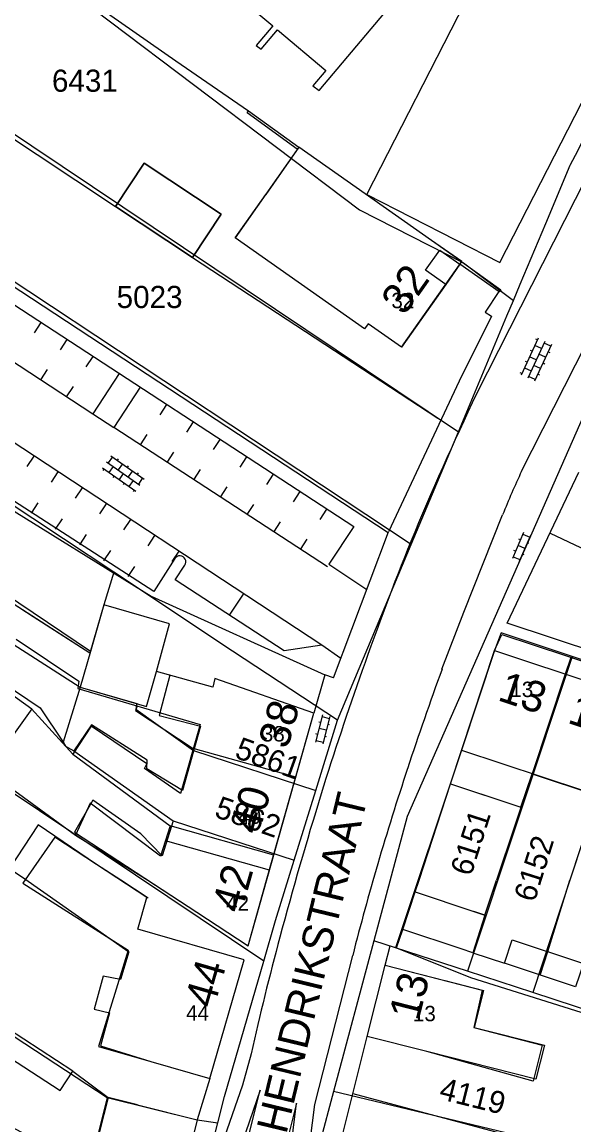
# Model space of a CAD drawing. Extents: x 148816 to 151297, y 399515 to 402500.
# Drawn here: x 150544.5 to 150589.4, y 399730.1 to 399819.8 of the extents above; entities that cross this region are included whole.
import ezdxf

# ---------------------------------------------------------------- set-up
doc = ezdxf.new("R2010")
doc.units = 0
for name, color, linetype in [('B01 Hoofdgebouw  [D] Norm', 7, 'Continuous'), ('B01 Hoofdgebouw  [T] Norm', 7, 'Continuous'), ('B01 hoofgebouw', 7, 'Continuous'), ('B02 Bijgebouw  [D] Norm', 7, 'Continuous'), ('B03 Overig opstal  [D] Norm', 7, 'Continuous'), ('B07 Tussenmuur  [D] Norm', 7, 'Continuous'), ('G01 perceelsgrens', 7, 'Continuous'), ('Q19 Overig lijnvormig object  [D] Gem', 7, 'Continuous'), ('S02 Open verharding  Norm', 7, 'Continuous'), ('T01 Muur  [T] Gem', 7, 'Continuous'), ('T04 Haag heg  [D] Gem', 7, 'Continuous'), ('V00 Kant verharding algemeen  [T] Norm', 7, 'Continuous'), ('V00 Kant verharding algemeen secundair  [T] Gem', 7, 'Continuous'), ('Z01 perceelnummer', 7, 'Continuous'), ('Z02 huisnummer', 7, 'Continuous'), ('Z02 Huisnummer  [Tekst] Norm', 7, 'Continuous'), ('Z06 straatnaam', 7, 'Continuous')]:
    doc.layers.add(name, color=color, linetype=linetype)

msp = doc.modelspace()

# ---------------------------------------------------------------- linework, layer by layer
at = {"layer": 'B01 Hoofdgebouw  [D] Norm'}
for p, q in [((150567.028, 399809.594), (150561.87, 399802.23)), ((150544.071, 399769.604), (150549.156, 399766.191)), ((150549.156, 399766.191), (150549.081, 399765.583)), ((150549.081, 399765.583), (150559.014, 399762.662)), ((150550.155, 399762.541), (150548.663, 399760.255)), ((150554.681, 399759.457), (150550.155, 399762.541)), ((150559.014, 399762.662), (150557.428, 399757.054)), ((150548.663, 399760.255), (150556.597, 399754.414)), ((150554.504, 399759.076), (150554.681, 399759.457)), ((150557.428, 399757.054), (150554.504, 399759.076)), ((150550.094, 399756.277), (150548.882, 399753.661)), ((150555.791, 399751.952), (150550.094, 399756.277)), ((150545.86, 399754.517), (150543.533, 399750.961)), ((150550.61, 399751.29), (150545.86, 399754.517)), ((150556.597, 399754.414), (150555.791, 399751.952)), ((150565.001, 399752.042), (150556.597, 399754.414)), ((150548.882, 399753.661), (150554.773, 399750)), ((150564.655, 399750.815), (150556.2, 399753.201)), ((150543.533, 399750.961), (150544.779, 399750.127)), ((150544.779, 399750.127), (150553.223, 399744.181)), ((150554.773, 399750), (150558.74, 399747.4)), ((150553.223, 399744.181), (150552.549, 399741.944)), ((150586.642, 399742.299), (150587.27, 399744.198)), ((150551.151, 399742.217), (150550.404, 399739.523)), ((150552.549, 399741.944), (150551.151, 399742.217)), ((150550.404, 399739.523), (150551.65, 399739.224)), ((150551.65, 399739.224), (150550.928, 399736.53)), ((150550.928, 399736.53), (150555, 399735.27)), ((150551.538, 399732.332), (150550.091, 399726.654)), ((150553.92, 399731.74), (150551.538, 399732.332))]:
    msp.add_line(p, q, dxfattribs=at)
for points in [[(150579.368, 399757.845), (150585.088, 399755.952), (150585.991, 399758.667), (150596.457, 399755.187)], [(150581.948, 399741.073), (150581.259, 399738.024), (150586.801, 399736.605)], [(150586.801, 399736.605), (150586.08, 399733.683), (150577.44, 399736.07)]]:
    msp.add_lwpolyline(points, dxfattribs=at)
at = {"layer": 'B01 Hoofdgebouw  [T] Norm'}
for p, q in [((150552.15, 399804.78), (150554.48, 399808.3)), ((150554.48, 399808.3), (150560.73, 399804.15)), ((150558.39, 399800.64), (150552.15, 399804.78)), ((150560.73, 399804.15), (150558.39, 399800.64)), ((150572.38, 399794.84), (150561.87, 399802.23)), ((150578.98, 399798.44), (150575.39, 399793.34)), ((150572.67, 399795.23), (150572.38, 399794.84)), ((150575.39, 399793.34), (150572.67, 399795.23)), ((150545.46, 399771.43), (150540.22, 399774.78)), ((150551.19, 399772.4), (150550.06, 399768.47)), ((150556.54, 399770.86), (150551.19, 399772.4)), ((150550.06, 399768.47), (150545.46, 399771.43)), ((150555.46, 399766.97), (150556.54, 399770.86)), ((150579.368, 399757.845), (150582.95, 399768.67)), ((150582.95, 399768.67), (150599.64, 399763.12)), ((150560.04, 399765.7), (150555.46, 399766.97)), ((150560.22, 399766.41), (150560.04, 399765.7)), ((150568.26, 399763.59), (150560.22, 399766.41)), ((150564.425, 399750), (150568.26, 399763.59)), ((150552.58, 399750), (150550.61, 399751.29)), ((150554.79, 399748.55), (150552.58, 399750)), ((150562.92, 399744.66), (150564.425, 399750)), ((150575.49, 399746), (150576.5, 399749.05)), ((150576.5, 399749.05), (150581.25, 399747.47)), ((150553.95, 399746.02), (150554.7, 399748.61)), ((150558.74, 399747.4), (150562.92, 399744.66)), ((150562.59, 399743.53), (150553.95, 399746.02)), ((150580.23, 399744.42), (150575.49, 399746)), ((150559.81, 399733.88), (150562.59, 399743.53)), ((150572.59, 399737.3), (150574.06, 399743.09)), ((150574.06, 399743.09), (150581.948, 399741.073)), ((150577.44, 399736.07), (150572.59, 399737.3)), ((150555, 399735.27), (150559.81, 399733.88)), ((150553.92, 399731.74), (150558.78, 399730.54)), ((150558.78, 399730.54), (150555, 399715.27))]:
    msp.add_line(p, q, dxfattribs=at)
msp.add_lwpolyline([(150578.98, 399798.44), (150577.34, 399799.59), (150578.49, 399801.227), (150580.129, 399800.078), (150580.277, 399800.266), (150567.028, 399809.594)], dxfattribs=at)
at = {"layer": 'B01 hoofgebouw'}
for points in [[(150577.83, 399802.01), (150567.036, 399809.584), (150564.35, 399805.76)], [(150552.15, 399804.78), (150558.39, 399800.64), (150560.73, 399804.15), (150554.48, 399808.3), (150552.15, 399804.78)], [(150575.39, 399793.34), (150572.67, 399795.23), (150572.38, 399794.84), (150561.87, 399802.23), (150564.35, 399805.76)], [(150575.39, 399793.34), (150580.278, 399800.291), (150577.83, 399802.01)], [(150558.74, 399747.4), (150562.92, 399744.66), (150568.26, 399763.59), (150560.22, 399766.41), (150560.04, 399765.7), (150555.46, 399766.97), (150556.54, 399770.86), (150551.19, 399772.4), (150550.06, 399768.47), (150540.22, 399774.78), (150539.07, 399772.99)], [(150539.07, 399772.99), (150538.728, 399772.454), (150549.263, 399765.698), (150554.674, 399764.14), (150555.46, 399766.97)], [(150579.368, 399757.845), (150582.95, 399768.67), (150599.64, 399763.12), (150598.91, 399760.86), (150620.1, 399753.84), (150620.85, 399756.1), (150632.13, 399752.36), (150630.56, 399747.62)], [(150556.57, 399766.662), (150555.69, 399763.406), (150559.036, 399762.518), (150557.585, 399757.294), (150554.685, 399759.06), (150554.714, 399759.754), (150550.195, 399762.627), (150548.768, 399760.515), (150556.832, 399754.828), (150555.925, 399751.979), (150554.192, 399753.766), (150550.299, 399756.503), (150548.822, 399753.901), (150558.74, 399747.4)], [(150580.269, 399760.57), (150596.652, 399755.155), (150596.036, 399753.294), (150618.026, 399746.009), (150618.684, 399747.993), (150629.497, 399744.411), (150630.56, 399747.62)], [(150579.368, 399757.845), (150584.115, 399756.274)], [(150550.61, 399751.29), (150547.224, 399753.509), (150544.598, 399749.759), (150553.184, 399744.316), (150550.754, 399736.497), (150555, 399735.27)], [(150555, 399735.27), (150559.81, 399733.88), (150562.59, 399743.53), (150553.95, 399746.02), (150554.699, 399748.61), (150550.61, 399751.29)], [(150580.23, 399744.421), (150575.49, 399746), (150576.5, 399749.05), (150581.25, 399747.47)], [(150581.25, 399747.47), (150582.166, 399747.165), (150581.177, 399744.106), (150580.23, 399744.421)], [(150577.44, 399736.07), (150572.59, 399737.3), (150574.06, 399743.09), (150578.91, 399741.85)], [(150578.91, 399741.85), (150582.042, 399741.049), (150581.277, 399738.037), (150586.991, 399736.586), (150586.292, 399733.831), (150577.44, 399736.07)], [(150553.92, 399731.74), (150551.463, 399732.347), (150550.034, 399726.575), (150540.675, 399731.527), (150539.134, 399728.318), (150549.308, 399723.108), (150547.671, 399717.193), (150554.88, 399715.29)], [(150553.92, 399731.74), (150558.78, 399730.54), (150555, 399715.27), (150554.88, 399715.29), (150554.11, 399712.06), (150554.34, 399711.91), (150545.9, 399698.83), (150538.61, 399703.59), (150541.34, 399707.78)]]:
    msp.add_lwpolyline(points, dxfattribs=at)
at = {"layer": 'B02 Bijgebouw  [D] Norm'}
for p, q in [((150582.166, 399747.165), (150581.25, 399747.47)), ((150582.166, 399747.165), (150581.177, 399744.106)), ((150581.177, 399744.106), (150580.23, 399744.42))]:
    msp.add_line(p, q, dxfattribs=at)
for points in [[(150545.354, 399763.926), (150542.124, 399759.47), (150539.598, 399761.301), (150542.828, 399765.757)], [(150584.379, 399745.154), (150590.163, 399743.242), (150589.535, 399741.343), (150583.751, 399743.255)], [(150548.679, 399734.489), (150543.371, 399737.938), (150542.347, 399736.362), (150547.655, 399732.913)]]:
    msp.add_lwpolyline(points, close=True, dxfattribs=at)
at = {"layer": 'B03 Overig opstal  [D] Norm'}
msp.add_line((150580.129, 399800.078), (150578.98, 399798.44), dxfattribs=at)
at = {"layer": 'B07 Tussenmuur  [D] Norm'}
for p, q in [((150588.683, 399766.764), (150585.991, 399758.667)), ((150588.683, 399766.764), (150585.991, 399758.667)), ((150566.788, 399758.373), (150558.465, 399760.722)), ((150566.788, 399758.373), (150558.465, 399760.722))]:
    msp.add_line(p, q, dxfattribs=at)
at = {"layer": 'G01 perceelsgrens'}
for points in [[(150589.099, 399808.13), (150589.122, 399808.185), (150589.71, 399809.3), (150601.431, 399833.535), (150603.833, 399838.516)], [(150545.002, 399824.898), (150571.96, 399804.509)], [(150604.416, 399818.758), (150601.281, 399812.394), (150599.073, 399807.818), (150596.886, 399803.311), (150590.138, 399787.704), (150575.84, 399755.196), (150573.128, 399745.085)], [(150537.849, 399814.725), (150580.009, 399786.458)], [(150587.102, 399803.381), (150589.099, 399808.13)], [(150576.166, 399777.284), (150532.256, 399806.347)], [(150571.96, 399804.509), (150580.411, 399800.191)], [(150585.036, 399798.471), (150587.102, 399803.381)], [(150580.411, 399800.191), (150584.475, 399797.137)], [(150584.475, 399797.137), (150585.036, 399798.471)], [(150580.009, 399786.458), (150583.954, 399795.897), (150584.475, 399797.137)], [(150551.994, 399775.056), (150547.928, 399777.763), (150525.787, 399792.428)], [(150550.097, 399768.597), (150522.284, 399787.353)], [(150576.166, 399777.284), (150577.906, 399781.427), (150580.009, 399786.458)], [(150518.839, 399782.361), (150546.033, 399764.013), (150547.883, 399761.218)], [(150570.17, 399763.009), (150576.166, 399777.284)], [(150564.198, 399743.427), (150519.987, 399773.049), (150514.769, 399776.465)], [(150551.994, 399775.056), (150551.19, 399772.4), (150550.097, 399768.597)], [(150570.17, 399763.009), (150561.645, 399768.63), (150551.994, 399775.056)], [(150490.322, 399772.344), (150518.769, 399753.768), (150551.463, 399732.347), (150558.78, 399730.54), (150560.452, 399730.286)], [(150589.256, 399768.196), (150583.47, 399770.128), (150582.95, 399768.67), (150580.27, 399760.57), (150574.887, 399744.504)], [(150550.097, 399768.597), (150549.263, 399765.698)], [(150589.256, 399768.196), (150580.733, 399742.602)], [(150594.474, 399766.455), (150589.256, 399768.196)], [(150594.474, 399766.455), (150586.049, 399740.873)], [(150549.263, 399765.698), (150547.883, 399761.218)], [(150549.263, 399765.698), (150553.885, 399764.368), (150553.794, 399763.902), (150558.486, 399760.54), (150568.415, 399757.309)], [(150568.415, 399757.309), (150570.17, 399763.009)], [(150547.883, 399761.218), (150548.085, 399760.913), (150548.768, 399760.515), (150556.832, 399754.828), (150566.666, 399751.626)], [(150566.666, 399751.626), (150568.415, 399757.309)], [(150564.198, 399743.427), (150565.156, 399746.725), (150566.666, 399751.626)], [(150573.128, 399745.085), (150569.86, 399732.829)], [(150574.887, 399744.504), (150573.128, 399745.085)], [(150580.733, 399742.602), (150574.887, 399744.504)], [(150560.452, 399730.286), (150561.002, 399732.427), (150564.198, 399743.427)], [(150586.049, 399740.873), (150580.733, 399742.602)], [(150591.249, 399739.182), (150586.049, 399740.873)], [(150569.86, 399732.829), (150566.525, 399720.322)], [(150593.91, 399727.057), (150569.86, 399732.829)], [(150558.519, 399722.699), (150558.929, 399724.354), (150560.452, 399730.286)]]:
    msp.add_lwpolyline(points, dxfattribs=at)
at = {"layer": 'Q19 Overig lijnvormig object  [D] Gem'}
for points in [[(150572.578, 399805.753), (150583.374, 399800.222), (150593.34, 399819.673), (150589.308, 399823.073), (150592.705, 399827.102), (150593.685, 399826.275), (150601.304, 399835.311), (150600.645, 399835.867), (150604.332, 399840.24), (150601.121, 399842.948), (150606.381, 399849.186), (150592.425, 399860.953), (150592.045, 399860.502)], [(150560.987, 399822.769), (150564.914, 399819.459), (150563.571, 399817.866), (150563.98, 399817.575), (150565.296, 399819.136), (150569.223, 399815.826), (150568.175, 399814.583), (150568.689, 399814.217), (150580.082, 399827.726)], [(150572.578, 399805.753), (150580.567, 399821.346), (150581.76, 399820.735), (150582.121, 399821.44)]]:
    msp.add_lwpolyline(points, dxfattribs=at)
at = {"layer": 'S02 Open verharding  Norm'}
for p, q in [((150586.487, 399794.061), (150585.102, 399791.066)), ((150586.424, 399793.925), (150586.288, 399793.988)), ((150587.031, 399793.81), (150585.647, 399790.814)), ((150586.004, 399793.018), (150585.868, 399793.081)), ((150587.576, 399793.558), (150586.191, 399790.563)), ((150586.759, 399793.22), (150586.214, 399793.471)), ((150587.513, 399793.422), (150586.969, 399793.674)), ((150587.303, 399792.968), (150587.439, 399792.905)), ((150585.585, 399792.11), (150585.448, 399792.173)), ((150586.339, 399792.312), (150585.794, 399792.564)), ((150587.093, 399792.514), (150586.549, 399792.766)), ((150586.884, 399792.06), (150587.02, 399791.997)), ((150585.165, 399791.202), (150585.029, 399791.265)), ((150585.375, 399791.656), (150585.919, 399791.404)), ((150586.674, 399791.606), (150586.129, 399791.858)), ((150586.464, 399791.153), (150586.6, 399791.09)), ((150586.254, 399790.699), (150585.709, 399790.95)), ((150551.421, 399784.016), (150554.127, 399782.128)), ((150551.887, 399784.422), (150551.544, 399783.93)), ((150551.764, 399784.508), (150554.471, 399782.62)), ((150552.297, 399784.136), (150552.383, 399784.259)), ((150551.077, 399783.524), (150553.784, 399781.636)), ((150551.201, 399783.438), (150551.115, 399783.315)), ((150551.954, 399783.644), (150551.611, 399783.152)), ((150552.707, 399783.85), (150552.364, 399783.358)), ((150553.117, 399783.564), (150553.203, 399783.687)), ((150553.527, 399783.278), (150553.184, 399782.786)), ((150553.937, 399782.992), (150554.023, 399783.115)), ((150552.021, 399782.866), (150551.935, 399782.743)), ((150552.774, 399783.072), (150552.431, 399782.58)), ((150552.841, 399782.294), (150552.755, 399782.171)), ((150553.251, 399782.008), (150553.594, 399782.5)), ((150554.347, 399782.706), (150554.004, 399782.214)), ((150553.661, 399781.722), (150553.575, 399781.599)), ((150585.308, 399778.276), (150584.393, 399776.166)), ((150585.05, 399777.68), (150584.912, 399777.74)), ((150585.859, 399778.038), (150584.944, 399775.928)), ((150585.249, 399778.139), (150585.799, 399777.9)), ((150584.652, 399776.763), (150584.514, 399776.822)), ((150585.401, 399776.983), (150584.851, 399777.221)), ((150585.738, 399777.382), (150585.6, 399777.441)), ((150584.453, 399776.304), (150585.003, 399776.065)), ((150585.34, 399776.464), (150585.202, 399776.524)), ((150568.965, 399763.457), (150568.401, 399761.228)), ((150568.806, 399762.827), (150568.66, 399762.864)), ((150568.928, 399763.312), (150569.51, 399763.165)), ((150569.547, 399763.31), (150568.983, 399761.081)), ((150569.533, 399762.643), (150569.387, 399762.68)), ((150568.561, 399761.858), (150568.415, 399761.895)), ((150569.265, 399762.195), (150568.683, 399762.343)), ((150569.288, 399761.674), (150569.142, 399761.711)), ((150568.438, 399761.373), (150569.02, 399761.226))]:
    msp.add_line(p, q, dxfattribs=at)
at = {"layer": 'T01 Muur  [T] Gem'}
for points in [[(150566.913, 399809.43), (150562.838, 399812.378), (150562.955, 399812.54), (150567.028, 399809.594)], [(150580.277, 399800.266), (150583.455, 399798.003), (150583.333, 399797.832), (150580.129, 399800.078)]]:
    msp.add_lwpolyline(points, dxfattribs=at)
at = {"layer": 'T04 Haag heg  [D] Gem'}
for p, q in [((150537.563, 399814.432), (150552.15, 399804.78)), ((150532.152, 399805.974), (150574.298, 399778.283)), ((150558.39, 399800.64), (150578.345, 399787.561)), ((150524.785, 399791.88), (150555.028, 399773.103)), ((150555.028, 399773.103), (150569.14, 399766.69)), ((150589.132, 399768.121), (150588.683, 399766.764)), ((150545.329, 399763.951), (150548.663, 399760.255)), ((150553.905, 399764.165), (150553.756, 399763.792)), ((150553.756, 399763.792), (150558.465, 399760.722)), ((150537.236, 399762.158), (150548.882, 399753.661)), ((150585.991, 399758.667), (150583.109, 399750)), ((150591.345, 399756.887), (150589.055, 399750)), ((150582.166, 399747.165), (150583.109, 399750)), ((150587.27, 399744.198), (150589.055, 399750)), ((150548.679, 399734.489), (150551.538, 399732.332)), ((150571.433, 399732.673), (150593.685, 399726.708))]:
    msp.add_line(p, q, dxfattribs=at)
msp.add_lwpolyline([(150545.036, 399825.01), (150557.051, 399816.621), (150562.955, 399812.54)], dxfattribs=at)
at = {"layer": 'V00 Kant verharding algemeen  [T] Norm'}
for p, q in [((150529.69, 399806.06), (150571.51, 399778.765)), ((150583.29, 399797.862), (150582.17, 399796.18)), ((150582.71, 399795.85), (150580.08, 399790.57)), ((150582.17, 399796.18), (150582.71, 399795.85)), ((150555.245, 399773.465), (150526.41, 399792.14)), ((150552.444, 399791.209), (150550.299, 399787.922)), ((150580.08, 399790.57), (150574.32, 399778.33)), ((150554.147, 399790.097), (150552.002, 399786.81)), ((150550.299, 399787.922), (150552.002, 399786.81)), ((150571.51, 399778.765), (150569.49, 399775.685)), ((150569.85, 399766.45), (150574.32, 399778.33)), ((150556.955, 399776.15), (150555.245, 399773.465)), ((150556.99, 399774.425), (150557.78, 399775.615)), ((150569.49, 399775.685), (150572.555, 399773.635)), ((150565.84, 399768.66), (150556.99, 399774.425)), ((150636.07, 399753.71), (150583.965, 399770.895)), ((150582.95, 399768.67), (150583.54, 399769.97)), ((150583.54, 399769.97), (150635.77, 399752.7)), ((150568.91, 399769.115), (150565.84, 399768.66)), ((150570.445, 399768.035), (150568.91, 399769.115)), ((150569.14, 399766.69), (150568.26, 399763.59)), ((150569.85, 399766.45), (150569.14, 399766.69)), ((150576.81, 399750), (150579.368, 399757.845)), ((150576.5, 399749.05), (150576.81, 399750)), ((150574.99, 399744.51), (150575.49, 399746)), ((150574.06, 399743.09), (150574.46, 399744.67)), ((150574.46, 399744.67), (150574.99, 399744.51)), ((150574.99, 399744.51), (150580.983, 399742.109)), ((150581.177, 399744.106), (150583.751, 399743.255)), ((150580.983, 399742.109), (150597.132, 399737.011)), ((150570.23, 399727.86), (150572.59, 399737.3)), ((150559.81, 399733.88), (150558.78, 399730.54))]:
    msp.add_line(p, q, dxfattribs=at)
for points in [[(150585.134, 399783.249), (150600.906, 399814.322), (150618.115, 399848.38)], [(150610.914, 399847.597), (150581.487, 399789.55)], [(150580.457, 399771.786), (150583.6, 399779.711)], [(150578.674, 399767.16), (150580.457, 399771.786)], [(150567.339, 399723.887), (150568.345, 399731.762), (150571.415, 399743.889)], [(150563.155, 399735.879), (150562.457, 399733.346), (150559.509, 399724.854), (150559.229, 399723.903), (150555.774, 399710.32), (150555.465, 399708.924), (150555.257, 399707.378), (150554.255, 399699.961), (150554.089, 399698.961), (150537.651, 399631.41), (150525.146, 399580.041)]]:
    msp.add_lwpolyline(points, dxfattribs=at)
for centre, radius, start, end in [((150802.707, 399683.934), 245.139, 154.47896, 157.5527), ((150662.891, 399747.434), 85.609, 155.26894, 157.85005), ((150782.563, 399693.768), 222.77, 157.91198, 160.79654), ((150557.37, 399775.886), 0.492, 326.54952, 147.52489), ((150807.347, 399683.162), 249.671, 160.36897, 162.79203), ((150868.214, 399662.226), 307.968, 160.07873, 161.67102), ((150809.606, 399681.92), 246.141, 161.73234, 163.61948), ((150887.333, 399659.038), 333.214, 162.89849, 164.98208), ((150779.583, 399690.831), 214.823, 163.64168, 165.70098), ((150788.265, 399685.364), 230.708, 164.92159, 167.35237)]:
    msp.add_arc(centre, radius, start, end, dxfattribs=at)
at = {"layer": 'V00 Kant verharding algemeen secundair  [T] Gem'}
for p, q in [((150568.91, 399769.115), (150528.641, 399795.575)), ((150539.735, 399794.817), (150550.299, 399787.922)), ((150545.551, 399794.509), (150546.098, 399795.346)), ((150547.661, 399793.131), (150548.208, 399793.968)), ((150549.77, 399791.752), (150550.317, 399792.589)), ((150546.063, 399790.681), (150546.61, 399791.518)), ((150548.172, 399789.302), (150548.719, 399790.139)), ((150555.768, 399787.843), (150556.315, 399788.68)), ((150569.365, 399775.478), (150552.002, 399786.81)), ((150557.936, 399786.426), (150558.483, 399787.263)), ((150554.17, 399785.393), (150554.717, 399786.23)), ((150560.104, 399785.009), (150560.651, 399785.846)), ((150544.972, 399783.648), (150545.521, 399784.484)), ((150556.338, 399783.976), (150556.885, 399784.813)), ((150562.272, 399783.592), (150562.819, 399784.429)), ((150546.936, 399782.358), (150547.485, 399783.194)), ((150558.506, 399782.559), (150559.053, 399783.396)), ((150583.965, 399770.895), (150589.8, 399783.19)), ((150564.44, 399782.175), (150564.987, 399783.012)), ((150548.901, 399781.068), (150549.45, 399781.904)), ((150560.674, 399781.142), (150561.221, 399781.979)), ((150566.608, 399780.758), (150567.155, 399781.595)), ((150545.314, 399779.843), (150545.863, 399780.679)), ((150550.865, 399779.778), (150551.414, 399780.614)), ((150562.842, 399779.725), (150563.389, 399780.562)), ((150568.776, 399779.341), (150569.323, 399780.178)), ((150547.279, 399778.553), (150547.828, 399779.389)), ((150552.829, 399778.488), (150553.378, 399779.324)), ((150565.01, 399778.308), (150565.557, 399779.145)), ((150549.243, 399777.263), (150549.792, 399778.099)), ((150554.794, 399777.198), (150555.343, 399778.034)), ((150567.178, 399776.891), (150567.725, 399777.728)), ((150587.454, 399778.211), (150604.184, 399770.331)), ((150551.207, 399775.973), (150551.756, 399776.809)), ((150556.758, 399775.908), (150557.307, 399776.744)), ((150553.172, 399774.683), (150553.721, 399775.519)), ((150561.415, 399771.542), (150562.537, 399773.265))]:
    msp.add_line(p, q, dxfattribs=at)
for points in [[(150561.494, 399723.353), (150563.91, 399732.936), (150560.672, 399723.574), (150561.494, 399723.353)], [(150565.558, 399722.279), (150565.754, 399723.102), (150566.86, 399731.876), (150564.529, 399722.562), (150565.558, 399722.279)]]:
    msp.add_lwpolyline(points, dxfattribs=at)

# ---------------------------------------------------------------- texts
at = {"layer": 'Z01 perceelnummer'}
for s, p in [('6431', (150546.978, 399814.1)), ('5023', (150552.234, 399796.519))]:
    msp.add_text(s, height=1.8, dxfattribs=at).set_placement(p)
for s, rotation, p in [('5861', 340.2379, (150561.738, 399759.991)), ('5862', 340.81625, (150560.088, 399755.185)), ('6151', 72.22025, (150581.029, 399750.259)), ('6152', 72.47443, (150586.194, 399748.143)), ('4119', 345.99156, (150578.362, 399732.238))]:
    msp.add_text(s, height=1.8, rotation=rotation, dxfattribs=at).set_placement(p)
at = {"layer": 'Z02 huisnummer'}
for s, rotation, p in [('32', 54.84846, (150575.615, 399795.832)), ('13', 341.58317, (150583.107, 399764.666)), ('38', 74.28275, (150566.119, 399760.6)), ('12', 341.63753, (150588.788, 399762.822)), ('40', 74.28275, (150563.79, 399753.634)), ('42', 74.21205, (150562.35, 399747.238)), ('44', 73.92083, (150560.128, 399739.502)), ('13', 75.75526, (150576.76, 399738.489))]:
    msp.add_text(s, height=2.5, rotation=rotation, dxfattribs=at).set_placement(p)
at = {"layer": 'Z02 Huisnummer  [Tekst] Norm'}
for s, p in [('32', (150574.56, 399796.505)), ('13', (150584.229, 399764.895)), ('38', (150564.038, 399761.285)), ('40', (150562.11, 399754.585)), ('42', (150561.13, 399747.52)), ('44', (150557.881, 399738.593)), ('13', (150576.31, 399738.54))]:
    msp.add_text(s, height=1.25, dxfattribs=at).set_placement(p)
at = {"layer": 'Z06 straatnaam'}
msp.add_text('PR. HENDRIKSTRAAT', height=2.5, rotation=76.40844, dxfattribs=at).set_placement((150564.489, 399722.969))

doc.saveas('drawing.dxf')
